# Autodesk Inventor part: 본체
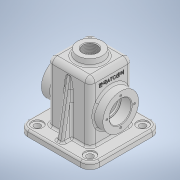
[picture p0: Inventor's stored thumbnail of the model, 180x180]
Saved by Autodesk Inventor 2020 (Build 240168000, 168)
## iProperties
Created: 2021-07
Part Number: 본체
Material: 일반
Document SubType Name: Modeling
Designer: Owner
Density: 1 g/cm^3
Appearance: 기본값
Mass: 278.261 g
Surface Area: 858.222 cm^2
Volume: 278.261 cm^3
Author: Owner
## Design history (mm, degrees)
sketch "스케치1"
  geometry: L1 (34, 34)-(-34, 34); L2 (-34, 34)-(-34, -34); L3 (-34, -34)-(34, -34); L4 (34, -34)-(34, 34); L5 (34, 34)-(-34, -34); L6 (-34, 34)-(34, -34); 1 further point
  constraints: 12 end point, 2 midpoint, 2 parallel, 1 horizontal, 1 perpendicular
  dimensions: "d0" = 68 distance of L3.end L2.end; "d1" = 68 distance of L2.end L1.end
extrude "돌출1" new body sketch "스케치1" distance "d2" = 95; taper "d3" = 0 deg
fillet "모깎기1" dims "d4" = 8
feature "쉘1" dims "d5" = 5
node "작업 평면1"
sketch "스케치2"
  geometry: C1 r 20 at (0, 0); 1 further point
  constraints: 1 centre point, 1 coincident
  dimensions: "d7" = 40 diameter of C1
extrude "돌출2" join sketch "스케치2" stored distance "d8" = 95; taper "d9" = 8 deg
sketch "스케치3"
  geometry: L1 (57, -57)-(-57, -57); L2 (-57, -57)-(-57, 57); L3 (-57, 57)-(57, 57); L4 (57, 57)-(57, -57); L5 (57, -57)-(-57, 57); L6 (-57, -57)-(57, 57); L7 (-29, -26)-(-29, 26) reference; L8 (26, -29)-(-26, -29) reference; L9 (29, 26)-(29, -26) reference; L10 (-26, 29)-(26, 29) reference; A1 r 3 centre (-26, -26) between (-29, -26) and (-26, -29) reference; A2 r 3 centre (26, -26) between (26, -29) and (29, -26) reference; A3 r 3 centre (-26, 26) between (-26, 29) and (-29, 26) reference; A4 r 3 centre (26, 26) between (29, 26) and (26, 29) reference; 1 further point
  constraints: 12 end point, 2 midpoint, 2 parallel, 1 horizontal, 1 perpendicular
  dimensions: "d10" = 114 distance of L2.end L3.end; "d11" = 114 distance of L1.end L2.end
extrude "돌출3" join sketch "스케치3" distance "d12" = 10; taper "d13" = 0 deg
fillet "모깎기2" dims "d14" = 15
sketch "스케치4"
  geometry: A1 r 15 centre (42, -42) between (42, -57) and (57, -42) reference; A2 r 15 centre (-42, -42) between (-57, -42) and (-42, -57) reference; A3 r 15 centre (42, 42) between (57, 42) and (42, 57) reference; A4 r 15 centre (-42, 42) between (-42, 57) and (-57, 42) reference; 5 further points
  constraints: 4 coincident
hole "구멍1" sketch "스케치4" at (42, -42), (-42, -42), (42, 42), (-42, 42) diameter "d15" = 10; stored, may be unused: countersink angle "d19" = 90 deg, drill point angle "d21" = 0 deg; dims "d16" = 8, "d17" = 18, "d18" = 2, "d20" = 10
sketch "스케치5"
  geometry: C1 r 20 at (0, 0) reference; 2 further points
  constraints: 1 coincident
hole "구멍2" sketch "스케치5" at (0, 0) diameter "d22" = 22.83494; stored, may be unused: countersink angle "d26" = 90 deg, drill point angle "d28" = 0 deg; dims "d23" = 20, "d24" = 18, "d25" = 2, "d27" = 20
node "작업 평면2"
sketch "스케치6"
  geometry: C1 r 28.5 at (42, 0); 1 further point
  constraints: 1 centre point, 1 horizontal alignment
  dimensions: "d30" = 57 diameter of C1; "d31" = 42 distance of point (0, 0) C1.centre
extrude "돌출4" join sketch "스케치6" stored distance "d32" = 10; taper "d33" = 0 deg
sketch "스케치7"
  geometry: C1 r 28.5 at (0, 0) reference; C2 r 17.5 at (0, 0); 1 further point
  constraints: 1 centre point, 1 coincident
  dimensions: "d34" = 35 diameter of C2
extrude "돌출5" cut sketch "스케치7" distance "d35" = 17; taper "d36" = 0 deg
sketch "스케치8"
  geometry: C1 r 17.5 at (0, 0) reference; C2 r 15 at (0, 0); 1 further point
  constraints: 1 centre point, 1 coincident
  dimensions: "d37" = 30 diameter of C2
extrude "돌출6" cut sketch "스케치8" stored distance "d38" = 17; taper "d39" = 0 deg
sketch "스케치9"
  geometry: L1 (6, 18)-(46, 18) reference; L2 (-8, 0)-(-8, -87) reference; 2 further points
  constraints: 1 other
  dimensions: "d40" = 25 distance from line of L1 point (26, -7); "d41" = 34 distance from line of L2 point (26, -7)
feature "엠보싱1" sketch "스케치9" dims "d0" = 68, "d1" = 68, "d42" = 0.5, "d43" = 0
sketch "스케치10" dims "d44" = 44
  geometry: C1 r 17.5 at (0, 0) reference; C2 r 15 at (0, 0) reference; 3 further points
  constraints: 2 vertical alignment, 1 coincident, 2 other
hole "구멍3" sketch "스케치10" at (0, 22) diameter "d45" = 3.242; stored, may be unused: countersink angle "d49" = 90 deg, drill point angle "d51" = 118 deg; dims "d46" = 8, "d47" = 18, "d48" = 2, "d50" = 10
sketch "스케치11"
  geometry: L1 (61.199, 38.209)-(0, 49); L2 (61.78, -38.107)-(0, -49); L3 (-10, 57)-(0, 57) reference; L4 (0, -57)-(-10, -57) reference; L5 (0, 51)-(0, 33) reference; L6 (0, 57)-(0, 42) reference; L7 (0, -33)-(0, -51) reference; L8 (0, -42)-(0, -57) reference; 1 further point
  constraints: 4 end point, 2 point on line
  dimensions: "d55" = 10 deg angle of L1 L3; "d56" = 10 deg angle of L2 L4; "d57" = 8 vertical distance of L3.start L1.end; "d58" = 8 distance from line of L4 L2.end
feature "리브1" sketch "스케치11" dims "d59" = 1, "d60" = 10, "d61" = 0, "d62" = 0, "d63" = 1, "d64" = 1
fillet "모깎기3" dims "d65" = 3
fillet "모깎기4" dims "d66" = 3
fillet "모깎기5" dims "d67" = 3
fillet "모깎기6" dims "d68" = 3
fillet "모깎기7" dims "d69" = 0.3
chamfer "모따기1" distance "d70" = 1; stored, may be unused: second distance "d71" = 2, angle "d72" = 45 deg
node "솔리드1"
mirror "미러1"
pattern_circular "원형 패턴1" dims angle "d53" = 360 deg
mirror "미러2"
mirror "미러3"
feature "A9D066F2-1C7D-4E18-AEED-F7BC21143FA4" dims "d15" = 10, "d16" = 8, "d17" = 18, "d18" = 2, "d19" = 90 deg, "d20" = 10, "d21" = 0
other parameters: "d6" = -105, "d29" = -49
